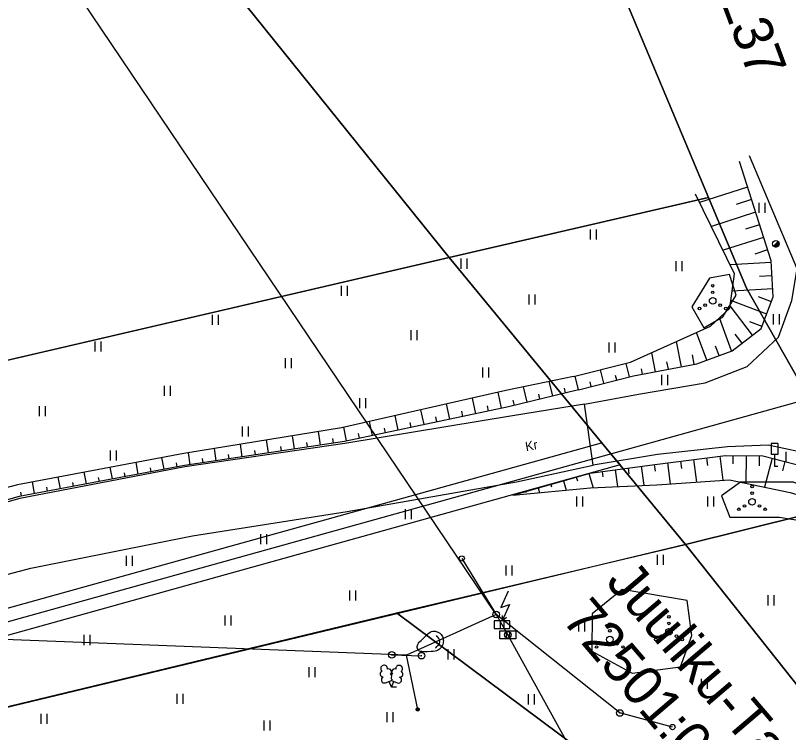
# Model space of a CAD drawing. Extents: x 532656 to 533339, y 6581345 to 6581629.
# Drawn here: x 533238.9 to 533297.5, y 6581493.4 to 6581547.8 of the extents above; entities that cross this region are included whole.
import ezdxf

# ---------------------------------------------------------------- set-up
doc = ezdxf.new("R2010")
doc.units = 0
for name, color, linetype in [('ELRAJATISMP', 7, 'Continuous'), ('HALJASTUS', 7, 'Continuous'), ('KASUTUSALA', 7, 'Continuous'), ('KPOHULIIN', 7, 'Continuous'), ('LIIKLUS', 7, 'Continuous'), ('MPOHULIIN', 7, 'Continuous'), ('PIIR', 7, 'Continuous'), ('POST', 7, 'Continuous'), ('PR_SIDE', 7, 'Continuous'), ('PUU', 7, 'Continuous'), ('RAJATIS', 7, 'Continuous'), ('RELJEEF', 7, 'Continuous'), ('TEE', 7, 'Continuous')]:
    doc.layers.add(name, color=color, linetype=linetype)

msp = doc.modelspace()

# ---------------------------------------------------------------- linework, layer by layer
at = {"layer": 'ELRAJATISMP'}
for p, q in [((533276.243, 6581504.146), (533275.674, 6581502.903)), ((533275.674, 6581502.903), (533276.322, 6581503.128)), ((533276.322, 6581503.128), (533275.767, 6581501.899)), ((533275.767, 6581502.295), (533275.767, 6581501.899)), ((533276.364, 6581501.899), (533275.169, 6581501.899)), ((533275.169, 6581501.899), (533275.169, 6581501.302)), ((533275.631, 6581501.899), (533275.631, 6581501.302)), ((533275.767, 6581501.899), (533276.097, 6581502.163)), ((533275.902, 6581501.899), (533275.902, 6581501.302)), ((533276.364, 6581501.302), (533276.364, 6581501.899)), ((533275.169, 6581501.302), (533276.364, 6581501.302)), ((533276.073, 6581501.132), (533276.073, 6581500.535)), ((533276.345, 6581501.132), (533276.345, 6581500.535))]:
    msp.add_line(p, q, dxfattribs=at)
msp.add_lwpolyline([(533275.612, 6581501.132), (533276.806, 6581501.132), (533276.806, 6581500.535), (533275.612, 6581500.535)], close=True, dxfattribs=at)
at = {"layer": 'HALJASTUS'}
for p, q in [((533295.237, 6581533.587), (533295.237, 6581532.826)), ((533295.692, 6581533.587), (533295.692, 6581532.826)), ((533282.457, 6581531.581), (533282.457, 6581530.82)), ((533282.912, 6581531.581), (533282.912, 6581530.82)), ((533272.65, 6581529.364), (533272.65, 6581528.603)), ((533273.105, 6581529.364), (533273.105, 6581528.603)), ((533288.939, 6581529.174), (533288.939, 6581528.413)), ((533289.394, 6581529.174), (533289.394, 6581528.413)), ((533263.577, 6581527.295), (533263.577, 6581526.534)), ((533264.032, 6581527.295), (533264.032, 6581526.534)), ((533277.798, 6581526.641), (533277.798, 6581525.879)), ((533278.253, 6581526.641), (533278.253, 6581525.879)), ((533296.334, 6581525.141), (533296.334, 6581524.38)), ((533296.789, 6581525.141), (533296.789, 6581524.38)), ((533253.786, 6581525.099), (533253.786, 6581524.338)), ((533254.241, 6581525.099), (533254.241, 6581524.338)), ((533268.852, 6581523.938), (533268.852, 6581523.177)), ((533269.307, 6581523.938), (533269.307, 6581523.177)), ((533244.882, 6581523.072), (533244.882, 6581522.311)), ((533245.337, 6581523.072), (533245.337, 6581522.311)), ((533283.875, 6581523.009), (533283.875, 6581522.248)), ((533284.33, 6581523.009), (533284.33, 6581522.248)), ((533259.315, 6581521.826), (533259.315, 6581521.065)), ((533259.77, 6581521.826), (533259.77, 6581521.065)), ((533274.295, 6581521.109), (533274.295, 6581520.347)), ((533274.751, 6581521.109), (533274.751, 6581520.347)), ((533287.852, 6581520.539), (533287.852, 6581519.777)), ((533288.307, 6581520.539), (533288.307, 6581519.777)), ((533250.157, 6581519.715), (533250.157, 6581518.954)), ((533250.612, 6581519.715), (533250.612, 6581518.954)), ((533264.969, 6581518.786), (533264.969, 6581518.025)), ((533265.424, 6581518.786), (533265.424, 6581518.025)), ((533240.662, 6581518.174), (533240.662, 6581517.413)), ((533241.117, 6581518.174), (533241.117, 6581517.413)), ((533256.065, 6581516.632), (533256.065, 6581515.871)), ((533256.52, 6581516.632), (533256.52, 6581515.871)), ((533246.064, 6581514.817), (533246.064, 6581514.055)), ((533246.519, 6581514.817), (533246.519, 6581514.055)), ((533297.284, 6581514.711), (533297.284, 6581513.95)), ((533281.417, 6581511.333), (533281.417, 6581510.572)), ((533281.872, 6581511.333), (533281.872, 6581510.572)), ((533291.334, 6581511.333), (533291.334, 6581510.572)), ((533291.789, 6581511.333), (533291.789, 6581510.572)), ((533268.419, 6581510.361), (533268.419, 6581509.6)), ((533268.874, 6581510.361), (533268.874, 6581509.6)), ((533257.447, 6581508.461), (533257.447, 6581507.7)), ((533257.902, 6581508.461), (533257.902, 6581507.7)), ((533247.277, 6581506.814), (533247.277, 6581506.053)), ((533247.732, 6581506.814), (533247.732, 6581506.053)), ((533287.536, 6581506.899), (533287.536, 6581506.138)), ((533287.991, 6581506.899), (533287.991, 6581506.138)), ((533276.057, 6581506.096), (533276.057, 6581505.335)), ((533276.512, 6581506.096), (533276.512, 6581505.335)), ((533264.199, 6581504.196), (533264.199, 6581503.435)), ((533264.654, 6581504.196), (533264.654, 6581503.435)), ((533295.923, 6581503.827), (533295.923, 6581503.066)), ((533296.378, 6581503.827), (533296.378, 6581503.066)), ((533254.746, 6581502.296), (533254.746, 6581501.535)), ((533255.202, 6581502.296), (533255.202, 6581501.535)), ((533281.575, 6581501.842), (533281.575, 6581501.081)), ((533282.03, 6581501.842), (533282.03, 6581501.081)), ((533244.07, 6581500.818), (533244.07, 6581500.057)), ((533244.525, 6581500.818), (533244.525, 6581500.057)), ((533271.658, 6581499.73), (533271.658, 6581498.969)), ((533272.113, 6581499.73), (533272.113, 6581498.969)), ((533261.108, 6581498.379), (533261.108, 6581497.618)), ((533261.563, 6581498.379), (533261.563, 6581497.618)), ((533290.859, 6581497.492), (533290.859, 6581496.731)), ((533291.314, 6581497.492), (533291.314, 6581496.731)), ((533251.107, 6581496.352), (533251.107, 6581495.591)), ((533251.562, 6581496.352), (533251.562, 6581495.591)), ((533277.74, 6581496.318), (533277.74, 6581495.557)), ((533278.195, 6581496.318), (533278.195, 6581495.557)), ((533240.81, 6581494.832), (533240.81, 6581494.071)), ((533241.265, 6581494.832), (533241.265, 6581494.071)), ((533267.021, 6581494.967), (533267.021, 6581494.205)), ((533267.476, 6581494.967), (533267.476, 6581494.205)), ((533257.695, 6581494.333), (533257.695, 6581493.572)), ((533258.15, 6581494.333), (533258.15, 6581493.572))]:
    msp.add_line(p, q, dxfattribs=at)
for points in [[(533292.5, 6581524.94), (533293.512, 6581526.593), (533293.016, 6581528.153), (533291.487, 6581527.871), (533290.163, 6581525.701), (533291.07, 6581524.104), (533292.5, 6581524.94)], [(533301.596, 6581509.531), (533301.205, 6581510.943), (533297.872, 6581512.419), (533293.85, 6581512.397), (533292.416, 6581511.385), (533293.032, 6581509.744), (533296.798, 6581509.751), (533300.946, 6581509.084), (533301.596, 6581509.531)], [(533290.158, 6581500.776), (533289.806, 6581503.429), (533284.874, 6581504.267), (533282.591, 6581502.416), (533282.579, 6581499.601), (533285.636, 6581497.932), (533289.291, 6581498.392), (533290.158, 6581500.776)]]:
    msp.add_lwpolyline(points, dxfattribs=at)
for centre, radius in [((533291.738, 6581527.309), 0.1), ((533291.738, 6581526.809), 0.1), ((533291.738, 6581526.159), 0.25), ((533291.173, 6581525.834), 0.1), ((533292.303, 6581525.834), 0.1), ((533290.738, 6581525.584), 0.1), ((533292.738, 6581525.584), 0.1), ((533294.721, 6581512.077), 0.1), ((533294.721, 6581511.577), 0.1), ((533294.721, 6581510.927), 0.25), ((533294.156, 6581510.602), 0.1), ((533295.286, 6581510.602), 0.1), ((533293.721, 6581510.352), 0.1), ((533295.721, 6581510.352), 0.1), ((533288.424, 6581502.2), 0.1), ((533283.938, 6581501.633), 0.1), ((533288.424, 6581501.7), 0.1), ((533283.938, 6581501.133), 0.1), ((533288.424, 6581501.05), 0.25), ((533283.938, 6581500.483), 0.25), ((533287.424, 6581500.475), 0.1), ((533287.859, 6581500.725), 0.1), ((533288.989, 6581500.725), 0.1), ((533289.424, 6581500.475), 0.1), ((533282.938, 6581499.908), 0.1), ((533283.373, 6581500.158), 0.1), ((533284.503, 6581500.158), 0.1), ((533284.938, 6581499.908), 0.1)]:
    msp.add_circle(centre, radius, dxfattribs=at)
at = {"layer": 'KASUTUSALA'}
msp.add_lwpolyline([(533130.587, 6581473.142), (533152.459, 6581478.238), (533179.669, 6581486.552), (533283.321, 6581515.401), (533284.712, 6581513.713), (533180.229, 6581484.632), (533152.978, 6581476.306), (533130.881, 6581471.157)], dxfattribs=at)
at = {"layer": 'KPOHULIIN'}
msp.add_lwpolyline([(533284.7, 6581494.901), (533275.324, 6581502.368), (533233.403, 6581564.579)], dxfattribs=at)
at = {"layer": 'LIIKLUS'}
for p, q in [((533296.18, 6581515.347), (533296.18, 6581514.497)), ((533296.68, 6581515.347), (533296.18, 6581515.347)), ((533296.68, 6581515.347), (533296.68, 6581514.497)), ((533296.68, 6581514.497), (533296.18, 6581514.497)), ((533296.43, 6581514.497), (533296.43, 6581513.597)), ((533296.68, 6581513.597), (533296.43, 6581513.597))]:
    msp.add_line(p, q, dxfattribs=at)
at = {"layer": 'MPOHULIIN'}
msp.add_line((533281.468, 6581491.312), (533276.209, 6581500.833), dxfattribs=at)
msp.add_lwpolyline([(533275.324, 6581502.368), (533268.528, 6581499.278), (533228.294, 6581500.866), (533187.877, 6581502.842), (533141.428, 6581504.881), (533095.447, 6581506.847), (533050.545, 6581508.805), (533010.87, 6581510.537), (532997.696, 6581528.314)], dxfattribs=at)
at = {"layer": 'PIIR'}
for points in [[(533261.482, 6581605.423), (533291.41, 6581534.01), (533271.76, 6581529.44), (533221.38, 6581591.97), (533256.874, 6581605.423)], [(533309.595, 6581500.161), (533303.4, 6581511.09), (533294.3, 6581527.13), (533291.41, 6581534.01), (533261.482, 6581605.423)], [(532997.696, 6581510.35), (533125.12, 6581495.35), (533271.76, 6581529.44), (533289.68, 6581507.68), (533127.07, 6581468.59), (533126.77, 6581469.47), (532997.696, 6581484.842)], [(533309.595, 6581482.585), (533289.68, 6581507.68), (533303.4, 6581511.09), (533309.595, 6581500.161)], [(533309.595, 6581464.945), (533292.38, 6581484.15), (533267.77, 6581502.5), (533289.68, 6581507.68), (533309.595, 6581482.585)], [(533141.128, 6581421.679), (533127.07, 6581468.59), (533267.77, 6581502.5), (533292.38, 6581484.15), (533309.595, 6581464.945)]]:
    msp.add_lwpolyline(points, dxfattribs=at)
for points in [[(533221.38, 6581591.97), (533271.76, 6581529.44), (533205.25, 6581513.98), (533173.8, 6581529.09), (533143.65, 6581562.67), (533194.1, 6581581.68)], [(533291.41, 6581534.01), (533294.3, 6581527.13), (533303.4, 6581511.09), (533289.68, 6581507.68), (533271.76, 6581529.44)]]:
    msp.add_lwpolyline(points, close=True, dxfattribs=at)
at = {"layer": 'POST'}
msp.add_line((533296.35, 6581530.309), (533296.704, 6581530.663), dxfattribs=at)
for points in [[(533272.716, 6581506.623), (533275.324, 6581502.368)], [(533269.37, 6581495.173), (533268.528, 6581499.278)], [(533288.687, 6581493.833), (533284.7, 6581494.901)]]:
    msp.add_lwpolyline(points, dxfattribs=at)
for centre, radius in [((533296.527, 6581530.486), 0.25), ((533272.716, 6581506.623), 0.2), ((533275.324, 6581502.368), 0.25), ((533275.324, 6581502.368), 0.0234), ((533276.209, 6581500.833), 0.25), ((533276.209, 6581500.833), 0.0234), ((533267.402, 6581499.306), 0.25), ((533267.402, 6581499.306), 0.0234), ((533269.653, 6581499.249), 0.25), ((533269.653, 6581499.249), 0.0234), ((533269.37, 6581495.173), 0.125), ((533269.37, 6581495.173), 0.105), ((533269.37, 6581495.173), 0.0851), ((533269.37, 6581495.173), 0.0651), ((533269.37, 6581495.173), 0.0451), ((533269.37, 6581495.173), 0.0251), ((533269.37, 6581495.173), 0.00511), ((533284.7, 6581494.901), 0.25), ((533284.7, 6581494.901), 0.0234), ((533288.687, 6581493.833), 0.2)]:
    msp.add_circle(centre, radius, dxfattribs=at)
for radius, start, end in [(0.225, 224.85406, 45.03563), (0.2, 224.84272, 45.04698), (0.175, 224.82813, 45.06157), (0.15, 224.80867, 45.08103), (0.125, 224.78144, 45.10826), (0.1, 224.74058, 45.14911), (0.075, 224.67249, 45.2172), (0.05, 224.53632, 45.35338), (0.025, 224.12776, 45.76193)]:
    msp.add_arc((533296.527, 6581530.486), radius, start, end, dxfattribs=at)
at = {"layer": 'PR_SIDE'}
msp.add_lwpolyline([(533009.759, 6581491.731), (533020.322, 6581490.227), (533026.333, 6581489.107), (533037.708, 6581487.732), (533062.593, 6581483.646), (533088.347, 6581480.21), (533108.952, 6581471.921), (533120.75, 6581471.502), (533130.735, 6581472.15), (533152.719, 6581477.273), (533179.95, 6581485.593), (533320.872, 6581524.815)], dxfattribs=at)
at = {"layer": 'PUU'}
for p, q in [((533266.94, 6581497.192), (533267.385, 6581497.367)), ((533267.38, 6581496.857), (533267.204, 6581497.297)), ((533267.38, 6581496.857), (533267.56, 6581497.297)), ((533267.385, 6581497.367), (533267.824, 6581497.187)), ((533267.76, 6581496.857), (533267.38, 6581496.857))]:
    msp.add_line(p, q, dxfattribs=at)
msp.add_lwpolyline([(533267.385, 6581497.862), (533267.365, 6581497.787), (533267.365, 6581497.767), (533267.375, 6581497.737), (533267.395, 6581497.702), (533267.4, 6581497.682), (533267.385, 6581497.647), (533267.36, 6581497.597), (533267.355, 6581497.572), (533267.36, 6581497.557), (533267.37, 6581497.527), (533267.405, 6581497.467), (533267.41, 6581497.447), (533267.405, 6581497.427), (533267.39, 6581497.392), (533267.385, 6581497.367)], dxfattribs=at)
for centre, radius, start, end in [((533266.822, 6581498.271), 0.256, 111.50269, 232.51731), ((533266.822, 6581498.271), 0.256, 350.48556, 111.50017), ((533267.157, 6581498.021), 0.224, 308.50412, 111.57247), ((533267.62, 6581498.016), 0.225, 67.7016, 230.51262), ((533267.958, 6581498.262), 0.256, 67.6168, 188.63142), ((533267.958, 6581498.262), 0.256, 306.59966, 67.61428), ((533266.749, 6581497.86), 0.224, 111.43041, 274.49868), ((533266.853, 6581497.415), 0.237, 111.50143, 291.50036), ((533267.384, 6581497.624), 0.237, 66.76552, 111.50149), ((533267.914, 6581497.407), 0.237, 247.61661, 67.61554), ((533268.026, 6581497.85), 0.224, 264.6183, 67.68657)]:
    msp.add_arc(centre, radius, start, end, dxfattribs=at)
at = {"layer": 'RAJATIS'}
for p, q in [((533275.324, 6581502.368), (533276.209, 6581500.833)), ((533267.402, 6581499.306), (533269.653, 6581499.249))]:
    msp.add_line(p, q, dxfattribs=at)
at = {"layer": 'RELJEEF'}
for p, q in [((533294.387, 6581534.789), (533290.751, 6581533.629)), ((533294.691, 6581533.837), (533293.526, 6581533.465)), ((533294.995, 6581532.884), (533291.639, 6581531.813)), ((533295.299, 6581531.931), (533294.227, 6581531.589)), ((533295.603, 6581530.979), (533292.526, 6581529.997)), ((533295.907, 6581530.026), (533294.928, 6581529.714)), ((533296.18, 6581529.068), (533293.066, 6581528.892)), ((533296.236, 6581528.069), (533295.277, 6581528.015)), ((533296.292, 6581527.071), (533293.22, 6581526.897)), ((533296.19, 6581526.097), (533295.214, 6581526.466)), ((533294.766, 6581523.561), (533293.069, 6581525.796)), ((533295.836, 6581525.161), (533293.123, 6581526.188)), ((533293.166, 6581522.365), (533292.244, 6581524.862)), ((533295.482, 6581524.226), (533294.554, 6581524.577)), ((533291.29, 6581521.672), (533290.518, 6581523.761)), ((533293.97, 6581522.956), (533293.449, 6581523.642)), ((533289.362, 6581521.166), (533288.994, 6581523.073)), ((533287.398, 6581520.787), (533287.12, 6581522.228)), ((533292.228, 6581522.018), (533291.963, 6581522.736)), ((533290.344, 6581521.355), (533290.206, 6581522.069)), ((533285.438, 6581520.391), (533285.182, 6581521.419)), ((533288.38, 6581520.976), (533288.272, 6581521.534)), ((533281.557, 6581519.424), (533281.301, 6581520.448)), ((533283.497, 6581519.908), (533283.242, 6581520.934)), ((533284.468, 6581520.149), (533284.382, 6581520.492)), ((533286.416, 6581520.597), (533286.339, 6581521)), ((533279.614, 6581518.948), (533279.347, 6581520.039)), ((533282.527, 6581519.666), (533282.442, 6581520.008)), ((533277.672, 6581518.472), (533277.387, 6581519.634)), ((533280.585, 6581519.186), (533280.499, 6581519.538)), ((533273.768, 6581517.6), (533273.519, 6581518.783)), ((533275.725, 6581518.013), (533275.469, 6581519.226)), ((533278.643, 6581518.71), (533278.551, 6581519.085)), ((533271.811, 6581517.187), (533271.568, 6581518.341)), ((533274.747, 6581517.806), (533274.662, 6581518.206)), ((533276.7, 6581518.234), (533276.603, 6581518.633)), ((533269.855, 6581516.774), (533269.617, 6581517.898)), ((533272.79, 6581517.393), (533272.708, 6581517.783)), ((533265.941, 6581515.948), (533265.716, 6581517.013)), ((533267.898, 6581516.361), (533267.667, 6581517.456)), ((533268.876, 6581516.567), (533268.798, 6581516.937)), ((533270.833, 6581516.98), (533270.753, 6581517.36)), ((533263.984, 6581515.535), (533263.765, 6581516.571)), ((533266.919, 6581516.154), (533266.843, 6581516.514)), ((533260.03, 6581514.929), (533259.879, 6581515.929)), ((533262.008, 6581515.227), (533261.854, 6581516.249)), ((533264.962, 6581515.742), (533264.888, 6581516.092)), ((533256.075, 6581514.332), (533255.931, 6581515.287)), ((533258.053, 6581514.63), (533257.905, 6581515.608)), ((533261.019, 6581515.078), (533260.968, 6581515.415)), ((533262.997, 6581515.376), (533262.945, 6581515.721)), ((533252.12, 6581513.735), (533251.982, 6581514.646)), ((533254.097, 6581514.034), (533253.957, 6581514.967)), ((533257.064, 6581514.481), (533257.015, 6581514.803)), ((533259.042, 6581514.779), (533258.992, 6581515.109)), ((533250.151, 6581513.383), (533249.984, 6581514.278)), ((533253.109, 6581513.884), (533253.062, 6581514.192)), ((533255.086, 6581514.183), (533255.039, 6581514.498)), ((533289.296, 6581514.004), (533289.366, 6581513.453)), ((533290.288, 6581514.13), (533290.506, 6581512.418)), ((533291.28, 6581514.257), (533291.355, 6581513.666)), ((533292.272, 6581514.383), (533292.505, 6581512.552)), ((533293.268, 6581514.435), (533293.262, 6581513.802)), ((533294.268, 6581514.425), (533294.248, 6581512.331)), ((533295.268, 6581514.415), (533295.261, 6581513.652)), ((533296.245, 6581514.228), (533295.676, 6581512.035)), ((533297.213, 6581513.977), (533297.027, 6581513.262)), ((533246.219, 6581512.65), (533246.054, 6581513.536)), ((533248.185, 6581513.016), (533248.019, 6581513.907)), ((533249.168, 6581513.2), (533249.113, 6581513.497)), ((533251.134, 6581513.567), (533251.079, 6581513.866)), ((533285.33, 6581513.484), (533285.391, 6581513.031)), ((533286.321, 6581513.617), (533286.515, 6581512.17)), ((533287.312, 6581513.75), (533287.381, 6581513.239)), ((533288.304, 6581513.877), (533288.507, 6581512.284)), ((533244.253, 6581512.283), (533244.089, 6581513.164)), ((533247.202, 6581512.833), (533247.147, 6581513.129)), ((533282.36, 6581513.072), (533282.669, 6581511.992)), ((533283.348, 6581513.218), (533283.401, 6581512.822)), ((533284.339, 6581513.351), (533284.51, 6581512.077)), ((533240.321, 6581511.549), (533240.158, 6581512.422)), ((533242.287, 6581511.916), (533242.123, 6581512.793)), ((533243.27, 6581512.099), (533243.215, 6581512.392)), ((533245.236, 6581512.466), (533245.181, 6581512.761)), ((533279.476, 6581512.244), (533279.527, 6581512.066)), ((533280.437, 6581512.52), (533280.642, 6581511.807)), ((533281.398, 6581512.796), (533281.484, 6581512.499)), ((533239.338, 6581511.365), (533239.284, 6581511.656)), ((533241.304, 6581511.732), (533241.25, 6581512.024)), ((533277.553, 6581511.693), (533277.57, 6581511.634)), ((533278.515, 6581511.969), (533278.617, 6581511.612))]:
    msp.add_line(p, q, dxfattribs=at)
for points in [[(533281.557, 6581519.424), (533285.742, 6581520.467), (533290.534, 6581521.392), (533293.214, 6581522.382), (533295.418, 6581524.056), (533296.327, 6581526.46), (533296.172, 6581529.195), (533293.772, 6581536.719)], [(533281.183, 6581520.419), (533285.51, 6581521.501), (533291.561, 6581524.231), (533293.042, 6581525.599), (533293.4, 6581528.208), (533290.443, 6581534.26)], [(533281.183, 6581520.419), (533276.051, 6581519.358), (533263.596, 6581516.532), (533251.647, 6581514.592), (533239.041, 6581512.211), (533226.47, 6581508.908), (533214.681, 6581505.256), (533201.89, 6581501.284), (533176.756, 6581494.489), (533164.986, 6581490.868), (533152.252, 6581486.88), (533140.456, 6581483.591), (533129.527, 6581479.745), (533118.624, 6581478.849), (533106.283, 6581479.431), (533097.704, 6581480.376), (533085.536, 6581482.555), (533072.437, 6581484.308), (533059.431, 6581486.026), (533046.012, 6581487.79), (533038.243, 6581488.575), (533036.77, 6581489.096), (533035.507, 6581491.062)], [(533281.557, 6581519.424), (533276.261, 6581518.126), (533263.818, 6581515.5), (533251.686, 6581513.67), (533239.149, 6581511.33), (533226.715, 6581507.822), (533214.835, 6581504.269), (533202.102, 6581500.222), (533189.776, 6581497.008), (533177.285, 6581493.009), (533165.345, 6581489.166), (533152.461, 6581485.112), (533140.732, 6581481.559), (533129.524, 6581478.53), (533118.474, 6581477.733), (533106, 6581477.895), (533097.29, 6581479.127), (533084.979, 6581481.19), (533071.975, 6581482.384), (533058.892, 6581484.144), (533045.84, 6581486.178), (533037.747, 6581487.165), (533036.173, 6581488.641), (533035.507, 6581491.062)], [(533276.592, 6581511.417), (533282.451, 6581513.098), (533287.357, 6581513.757), (533292.718, 6581514.44), (533295.532, 6581514.413), (533298.77, 6581513.572), (533302.044, 6581512.29), (533304.781, 6581509.803), (533308.425, 6581504.368), (533309.595, 6581502.271)], [(533276.592, 6581511.417), (533282.478, 6581511.983), (533287.494, 6581512.216), (533293.014, 6581512.587), (533297.606, 6581511.635), (533300.228, 6581510.847), (533301.844, 6581507.98), (533304.308, 6581503.346), (533307.513, 6581497.59)], [(533269.334, 6581499.948), (533269.353, 6581500.023), (533269.375, 6581500.088), (533269.397, 6581500.142), (533269.428, 6581500.199), (533269.479, 6581500.269), (533269.541, 6581500.332), (533269.626, 6581500.409), (533269.764, 6581500.535), (533269.853, 6581500.624), (533269.981, 6581500.756), (533270.054, 6581500.827), (533270.151, 6581500.911), (533270.226, 6581500.966), (533270.314, 6581501.02), (533270.423, 6581501.07), (533270.513, 6581501.097), (533270.609, 6581501.109), (533270.692, 6581501.105), (533270.778, 6581501.089), (533270.855, 6581501.064), (533270.955, 6581501.017), (533271.017, 6581500.978), (533271.099, 6581500.91), (533271.155, 6581500.85), (533271.213, 6581500.768), (533271.246, 6581500.705), (533271.278, 6581500.624), (533271.301, 6581500.541), (533271.314, 6581500.459), (533271.318, 6581500.375), (533271.315, 6581500.283), (533271.301, 6581500.188), (533271.277, 6581500.098), (533271.237, 6581500.004), (533271.195, 6581499.93), (533271.142, 6581499.857), (533271.082, 6581499.792), (533271.026, 6581499.744), (533270.953, 6581499.694), (533270.867, 6581499.651), (533270.793, 6581499.624), (533270.691, 6581499.598), (533270.555, 6581499.578), (533270.398, 6581499.563), (533270.101, 6581499.55), (533269.838, 6581499.549), (533269.682, 6581499.555), (533269.587, 6581499.568), (533269.513, 6581499.591), (533269.454, 6581499.623), (533269.407, 6581499.668), (533269.374, 6581499.724), (533269.351, 6581499.801), (533269.339, 6581499.876), (533269.334, 6581499.948)], [(533270.719, 6581499.818), (533270.762, 6581499.863), (533270.83, 6581499.936), (533270.898, 6581500.01), (533270.966, 6581500.083), (533271.022, 6581500.165), (533271.047, 6581500.262), (533271.048, 6581500.362), (533271.027, 6581500.459), (533270.984, 6581500.549), (533270.921, 6581500.627), (533270.856, 6581500.702), (533270.79, 6581500.778)]]:
    msp.add_lwpolyline(points, dxfattribs=at)
at = {"layer": 'TEE'}
for points in [[(533309.595, 6581504.516), (533306.388, 6581511.03), (533305.005, 6581512.072), (533302.788, 6581513.446), (533299.515, 6581514.457), (533295.949, 6581515.216), (533292.859, 6581515.08), (533287.545, 6581514.499), (533282.671, 6581513.706), (533282.015, 6581518.32), (533286.115, 6581519.072), (533291.163, 6581519.939), (533294.36, 6581521.188), (533296.727, 6581523.417), (533297.752, 6581526.189), (533298.149, 6581528.6), (533294.521, 6581537.152)], [(533282.015, 6581518.32), (533276.572, 6581517.43), (533263.842, 6581515.343), (533251.709, 6581513.563), (533239.208, 6581511.176), (533226.766, 6581507.719), (533214.907, 6581504.112), (533202.182, 6581499.975), (533189.925, 6581495.929), (533177.456, 6581491.89), (533165.589, 6581487.748), (533152.838, 6581483.598), (533140.892, 6581480.629), (533129.548, 6581478.319)], [(533130.592, 6581473.143), (533142.406, 6581475.798), (533154.705, 6581478.863), (533166.174, 6581482.418), (533178.498, 6581486.605), (533191.102, 6581490.849), (533203.463, 6581495.365), (533216.21, 6581499.377), (533227.788, 6581502.653), (533240.032, 6581505.882), (533252.309, 6581508.348), (533264.032, 6581510.189), (533276.864, 6581512.431), (533282.671, 6581513.706)]]:
    msp.add_lwpolyline(points, dxfattribs=at)

# ---------------------------------------------------------------- texts
at = {"layer": 'PIIR'}
for s, rotation, p in [('Juuliku-Tabasalu tee L37', 290.41304, (533278.968, 6581584.811)), ('Juuliku-Tabasalu tee L57', 310.48286, (533283.552, 6581504.796)), ('72501:001:1428', 310.48286, (533280.225, 6581501.956))]:
    msp.add_text(s, height=3, rotation=rotation, dxfattribs=at).set_placement(p)
at = {"layer": 'TEE'}
msp.add_text('Kr', height=0.7, rotation=10.4923, dxfattribs=at).set_placement((533277.597, 6581514.758))

doc.saveas('drawing.dxf')
